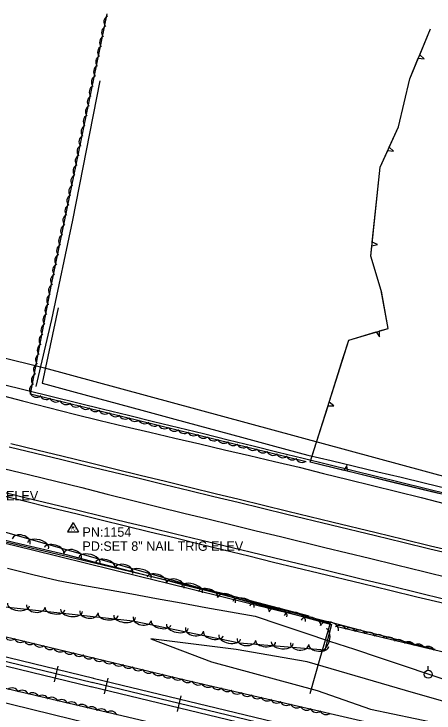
# Model space of a CAD drawing. Extents: x 1441650 to 1491889, y 345904 to 358319.
# Drawn here: x 1454791.4 to 1455015, y 352248.4 to 352621 of the extents above; entities that cross this region are included whole.
import ezdxf

# ---------------------------------------------------------------- set-up
doc = ezdxf.new("R2010")
doc.units = 0
for name, color, linetype in [('S_DITCHLINE', 7, 'Continuous'), ('S_EDGE_PAVEMENT', 7, 'Continuous'), ('S_PAVEMENT_CROWN', 7, 'Continuous'), ('S_RAILROAD', 7, 'Continuous'), ('S_SECONDARY_CTL', 7, 'Continuous'), ('S_SECONDARY_CTL_ANNOT', 7, 'Continuous'), ('S_SHOULDER', 7, 'Continuous'), ('S_STREAM', 7, 'Continuous'), ('S_TREE', 7, 'Continuous'), ('S_UTILITY_POLE', 7, 'Continuous'), ('S_UTL_PT_SYM', 7, 'Continuous'), ('S_WATER_UTILITIES', 7, 'Continuous')]:
    doc.layers.add(name, color=color, linetype=linetype)

msp = doc.modelspace()

# ---------------------------------------------------------------- linework, layer by layer
at = {"layer": 'S_DITCHLINE'}
for points in [[(1454784.38, 352423.88), (1454798.06, 352420.51), (1454811.75, 352417.13), (1454825.43, 352413.76), (1454839.11, 352410.38), (1454852.39, 352407.11), (1454865.67, 352403.83), (1454878.95, 352400.56), (1454892.23, 352397.28), (1454905.5, 352394.01), (1454918.78, 352390.73), (1454932.06, 352387.46), (1454945.34, 352384.18), (1454958.29, 352380.99), (1454971.24, 352377.8), (1454984.19, 352374.61), (1454997.14, 352371.42), (1455010.09, 352368.23), (1455023.04, 352365.04)], [(1454782.24, 352418.24), (1454796, 352414.73), (1454809.76, 352411.23), (1454823.53, 352407.72), (1454837.29, 352404.21), (1454850.54, 352401.1), (1454863.8, 352397.99), (1454877.05, 352394.88), (1454890.3, 352391.77), (1454903.55, 352388.66), (1454916.81, 352385.55), (1454930.06, 352382.45), (1454943.31, 352379.34), (1454956.28, 352376.1), (1454969.25, 352372.87), (1454982.22, 352369.64), (1454995.19, 352366.4), (1455008.16, 352363.17), (1455021.13, 352359.93)], [(1454778.21, 352342.58), (1454791.84, 352339.32), (1454805.47, 352336.06), (1454819.1, 352332.79), (1454831.95, 352329.52), (1454844.79, 352326.24), (1454857.63, 352322.96), (1454870.48, 352319.68), (1454883.32, 352316.4), (1454896.17, 352313.12), (1454909.01, 352309.84), (1454921.85, 352306.56), (1454935.24, 352303.1), (1454948.64, 352299.63), (1454962.03, 352296.17), (1454975.42, 352292.7), (1454988.81, 352289.24), (1455002.2, 352285.77), (1455015.59, 352282.31)], [(1454787.91, 352325.53), (1454801.39, 352322.23), (1454814.87, 352318.93), (1454827.98, 352316.55), (1454841.1, 352314.18), (1454854.21, 352311.81), (1454867.32, 352309.44), (1454880.44, 352307.06), (1454893.55, 352304.69), (1454906.67, 352302.32), (1454919.78, 352299.95), (1454933.01, 352295.54), (1454946.23, 352291.14), (1454959.46, 352286.73), (1454972.69, 352282.33), (1454985.91, 352277.92), (1454999.14, 352273.52), (1455012.37, 352269.11), (1455025.59, 352264.71)]]:
    msp.add_lwpolyline(points, dxfattribs=at)
at = {"layer": 'S_EDGE_PAVEMENT'}
for points in [[(1454788.75, 352390.31), (1454802.85, 352386.87), (1454816.94, 352383.43), (1454831.03, 352379.98), (1454844.51, 352376.74), (1454857.98, 352373.49), (1454871.46, 352370.24), (1454884.93, 352366.99), (1454897.86, 352363.84), (1454910.78, 352360.69), (1454923.71, 352357.54), (1454936.63, 352354.39), (1454960.28, 352348.65), (1454983.93, 352342.91), (1454998.39, 352339.42), (1455012.84, 352335.93), (1455027.29, 352332.43)], [(1454783.15, 352366.75), (1454797.23, 352363.31), (1454811.32, 352359.88), (1454825.41, 352356.44), (1454838.42, 352353.3), (1454851.43, 352350.16), (1454864.44, 352347.02), (1454877.46, 352343.88), (1454890.66, 352340.68), (1454903.87, 352337.48), (1454917.08, 352334.27), (1454930.29, 352331.07), (1454954.02, 352325.33), (1454977.75, 352319.59), (1454992.12, 352316.09), (1455006.5, 352312.6), (1455020.87, 352309.1)]]:
    msp.add_lwpolyline(points, dxfattribs=at)
at = {"layer": 'S_PAVEMENT_CROWN'}
msp.add_lwpolyline([(1454785.87, 352378.65), (1454799.75, 352375.26), (1454813.63, 352371.88), (1454827.51, 352368.49), (1454841.08, 352365.1), (1454854.65, 352361.71), (1454868.22, 352358.32), (1454881.79, 352354.93), (1454894.67, 352351.8), (1454907.55, 352348.66), (1454920.43, 352345.52), (1454933.31, 352342.39), (1454956.99, 352336.66), (1454980.66, 352330.94), (1454995.12, 352327.38), (1455009.57, 352323.82), (1455024.03, 352320.26)], dxfattribs=at)
at = {"layer": 'S_RAILROAD'}
for p, q in [((1454812.93, 352264.95), (1454814.98, 352273.38)), ((1454814.51, 352271.44), (1454814.49, 352271.33)), ((1454813.4, 352266.86), (1454813.41, 352266.89)), ((1454839.57, 352258.5), (1454841.61, 352266.93)), ((1454841.14, 352264.99), (1454841.11, 352264.89)), ((1454840.03, 352260.41), (1454840.04, 352260.45)), ((1454878.46, 352249.11), (1454880.49, 352257.54)), ((1454880.02, 352255.6), (1454880, 352255.49)), ((1454878.92, 352251.02), (1454878.93, 352251.05))]:
    msp.add_line(p, q, dxfattribs=at)
for points in [[(1454833.94, 352266.71), (1454392.82, 352374.01)], [(1454833.39, 352264.44), (1454392.26, 352371.74)], [(1454832.83, 352262.13), (1454391.7, 352369.44)], [(1454813.99, 352269.16), (1454813.96, 352269.16)], [(1455197.77, 352178.84), (1454833.57, 352266.82)], [(1455196.44, 352174.31), (1454832.46, 352262.24)], [(1455197.11, 352176.59), (1454833.02, 352264.55)], [(1454840.62, 352262.71), (1454840.59, 352262.72)], [(1454879.5, 352253.32), (1454879.47, 352253.32)]]:
    msp.add_lwpolyline(points, dxfattribs=at)
at = {"layer": 'S_SECONDARY_CTL'}
for p, q in [((1454822.83, 352349.94), (1454819.82, 352344.99)), ((1454822.83, 352349.94), (1454825.78, 352344.99)), ((1454819.82, 352344.99), (1454825.78, 352344.99))]:
    msp.add_line(p, q, dxfattribs=at)
for radius in [0.311, 0.183, 0.103]:
    msp.add_circle((1454822.83, 352347.33), radius, dxfattribs=at)
at = {"layer": 'S_SHOULDER'}
for points in [[(1454789.62, 352392.01), (1454803.56, 352388.61), (1454817.51, 352385.22), (1454831.45, 352381.82), (1454844.98, 352378.51), (1454858.5, 352375.2), (1454872.02, 352371.89), (1454885.54, 352368.58), (1454898.46, 352365.43), (1454911.37, 352362.27), (1454924.28, 352359.11), (1454937.2, 352355.95), (1454960.71, 352350.26), (1454984.22, 352344.57), (1454998.74, 352341.05), (1455013.25, 352337.53), (1455027.76, 352334.02)], [(1454782.72, 352364.85), (1454796.79, 352361.4), (1454810.86, 352357.95), (1454824.94, 352354.5), (1454837.89, 352351.34), (1454850.85, 352348.18), (1454863.8, 352345.02), (1454876.76, 352341.86), (1454889.96, 352338.61), (1454903.16, 352335.36), (1454916.36, 352332.11), (1454929.57, 352328.86), (1454953.29, 352323.12), (1454977.01, 352317.37), (1454991.47, 352313.86), (1455005.94, 352310.35), (1455020.41, 352306.83)]]:
    msp.add_lwpolyline(points, dxfattribs=at)
at = {"layer": 'S_STREAM'}
for points in [[(1454837.17, 352585.34), (1454822.46, 352511.1), (1454811.34, 352458.07), (1454803, 352422.49)], [(1454464.37, 352420.45), (1454584.76, 352390.45), (1454690.29, 352362.54), (1454900.85, 352312.56), (1454948.37, 352300.12)], [(1454471.1, 352326.84), (1454549.18, 352306.79), (1454623.89, 352291.03), (1454691.51, 352277.03), (1454779.52, 352255.49), (1454832.51, 352242.57), (1454893.03, 352228.02), (1454923.09, 352220.41), (1454992.68, 352203.26), (1455037.86, 352193.79)], [(1455059.44, 352243.37), (1455004.1, 352259.04), (1454947.56, 352275.57), (1454909.7, 352282.22), (1454864.17, 352287.88), (1454896.48, 352275.7), (1454952.86, 352260.44), (1454981.16, 352250.46), (1455040.76, 352237.99)]]:
    msp.add_lwpolyline(points, dxfattribs=at)
at = {"layer": 'S_TREE'}
for p, q in [((1455006.66, 352597.38), (1455009.79, 352597.1)), ((1455009.79, 352597.1), (1455007.42, 352599.2)), ((1454993.49, 352547.88), (1454991.18, 352550.06)), ((1454990.37, 352548.27), (1454993.49, 352547.88)), ((1454981.96, 352497.42), (1454985.04, 352498.05)), ((1454985.04, 352498.05), (1454982.16, 352499.37)), ((1454985.98, 352448.89), (1454986.1, 352452.05)), ((1454984.22, 352451.49), (1454985.98, 352448.89)), ((1454958.61, 352412.13), (1454961.75, 352412.13)), ((1454961.75, 352412.13), (1454959.2, 352414.01)), ((1454968.69, 352380.35), (1454966.99, 352377.68)), ((1454968.9, 352377.22), (1454968.69, 352380.35))]:
    msp.add_line(p, q, dxfattribs=at)
for points in [[(1454946.93, 352382.34), (1454800.22, 352418.34), (1454811.34, 352476.73), (1454825.66, 352546.64), (1454841.04, 352620.99)], [(1455082.97, 352349.51), (1454949.08, 352382.03), (1454969.69, 352447.17), (1454990.66, 352453.41), (1454986.98, 352473.63), (1454981.39, 352491.91), (1454986.32, 352539.42), (1454996.11, 352560.81), (1455002.09, 352586.46), (1455013.21, 352613.03)], [(1455007.42, 352599.2), (1455013.21, 352613.03)], [(1454999.1, 352573.64), (1455002.09, 352586.46), (1455006.66, 352597.38)], [(1454991.18, 352550.06), (1454996.11, 352560.81), (1454999.1, 352573.64)], [(1454984.74, 352524.24), (1454986.32, 352539.42), (1454990.37, 352548.27)], [(1454982.16, 352499.37), (1454984.74, 352524.24)], [(1454987.05, 352473.3), (1454986.98, 352473.63), (1454981.39, 352491.91), (1454981.96, 352497.42)], [(1454986.1, 352452.05), (1454990.66, 352453.41), (1454987.05, 352473.3)], [(1454814.94, 352464.41), (1454810.63, 352444.28), (1454806.32, 352424.15), (1454824.01, 352419.36), (1454841.7, 352414.58), (1454859.39, 352409.79), (1454877.07, 352405), (1454894.76, 352400.21), (1454912.45, 352395.42), (1454930.14, 352390.63), (1454947.82, 352385.84), (1454960.24, 352382.88), (1454972.65, 352379.92), (1454985.07, 352376.96), (1454997.48, 352374.01), (1455009.89, 352371.05), (1455022.31, 352368.09)], [(1454814.94, 352464.41), (1454810.63, 352444.28), (1454806.32, 352424.15), (1454824.01, 352419.36), (1454841.7, 352414.58), (1454859.39, 352409.79), (1454877.07, 352405), (1454894.76, 352400.21), (1454912.45, 352395.42), (1454930.14, 352390.63), (1454947.82, 352385.84), (1454960.24, 352382.88), (1454972.65, 352379.92), (1454985.07, 352376.96), (1454997.48, 352374.01), (1455009.89, 352371.05), (1455022.31, 352368.09)], [(1454966.74, 352437.84), (1454969.69, 352447.17), (1454984.22, 352451.49)], [(1454959.2, 352414.01), (1454966.74, 352437.84)], [(1454951.07, 352388.3), (1454958.61, 352412.13)], [(1454608.66, 352342.73), (1454569.35, 352351.26), (1454556.38, 352364.74), (1454562.37, 352384.23), (1454599.48, 352385.45), (1454764.41, 352351.11), (1454910.03, 352309.37), (1454960.45, 352295.62), (1454956.96, 352281.83), (1454911.55, 352285.58), (1454854.61, 352297.28), (1454786.67, 352304.84), (1454727.92, 352320.28), (1454664.77, 352330.43), (1454609.68, 352342.06)], [(1454966.99, 352377.68), (1454949.08, 352382.03), (1454951.07, 352388.3)], [(1454993.19, 352371.32), (1454968.9, 352377.22)], [(1454962.69, 352294.69), (1455082.43, 352265.99), (1455127.73, 352260.33), (1455171.95, 352246.67), (1455237.79, 352229.12), (1455266.56, 352215.9), (1455276.91, 352188.42), (1455269.69, 352172.72), (1455130.94, 352204.71), (1454988.1, 352241.29), (1454883.15, 352265.69), (1454742.86, 352299.41), (1454579.09, 352337.35), (1454448.11, 352370.53)], [(1455017.48, 352365.42), (1454993.19, 352371.32)], [(1454786.75, 352338.93), (1454801.16, 352335.37), (1454815.57, 352331.82), (1454829.99, 352328.27), (1454844.4, 352324.71), (1454858.82, 352321.16), (1454873.23, 352317.61), (1454887.65, 352314.05), (1454902.06, 352310.5), (1454916.48, 352306.94), (1454930.89, 352303.39), (1454945.3, 352299.84), (1454959.72, 352296.28), (1454954.33, 352277.44), (1454948.95, 352258.59)], [(1454786.75, 352338.93), (1454801.16, 352335.37), (1454815.57, 352331.82), (1454829.99, 352328.27), (1454844.4, 352324.71), (1454858.82, 352321.16), (1454873.23, 352317.61), (1454887.65, 352314.05), (1454902.06, 352310.5), (1454916.48, 352306.94), (1454930.89, 352303.39), (1454945.3, 352299.84), (1454959.72, 352296.28), (1454954.33, 352277.44), (1454948.95, 352258.59)], [(1454720.16, 352277.33), (1454872.99, 352241.33), (1454943.73, 352222.23), (1454977.97, 352214.82), (1455025.42, 352203.17), (1455102.25, 352183.63), (1455122.31, 352178.67), (1455138.5, 352175.87), (1455168.52, 352169.53), (1455253.06, 352148.2), (1455262.5, 352142.36), (1455264.98, 352131.4), (1455261.62, 352116.37)]]:
    msp.add_lwpolyline(points, dxfattribs=at)
for centre in [(1454842.86, 352616.65), (1454841.69, 352611.12), (1454840.58, 352605.8), (1454839.54, 352600.6), (1454838.54, 352595.41), (1454837.39, 352590.2), (1454836.21, 352584.68), (1454835.11, 352579.35), (1454834.07, 352574.15), (1454833.07, 352568.96), (1454831.92, 352563.75), (1454830.74, 352558.23), (1454829.64, 352552.9), (1454828.6, 352547.7)]:
    msp.add_arc(centre, 3.64, 117.5122, 219.1091, dxfattribs=at)
for centre, major_axis, ratio, start_param, end_param in [((1454827.61, 352542.51), (-3.63, 0.35), 0.999968, 5.289411, 7.062612), ((1454826.46, 352537.3), (-3.63, 0.35), 0.999968, 5.289411, 7.062612), ((1454825.3, 352531.78), (-3.63, 0.35), 0.999968, 5.289411, 7.062612), ((1454824.2, 352526.45), (-3.63, 0.35), 0.999968, 5.289411, 7.062612), ((1454823.17, 352521.25), (-3.63, 0.35), 0.999968, 5.289411, 7.062612), ((1454822.19, 352516.06), (-3.63, 0.35), 0.999968, 5.289411, 7.062612), ((1454821.04, 352510.85), (-3.63, 0.35), 0.999968, 5.289411, 7.062612), ((1454819.88, 352505.32), (-3.63, 0.35), 0.999968, 5.289411, 7.062612), ((1454818.78, 352499.99), (-3.63, 0.35), 0.999968, 5.289411, 7.062612), ((1454817.75, 352494.79), (-3.63, 0.35), 0.999968, 5.289411, 7.062612), ((1454816.76, 352489.6), (-3.63, 0.35), 0.999968, 5.289411, 7.062612), ((1454815.62, 352484.39), (-3.63, 0.35), 0.999968, 5.289411, 7.062612), ((1454814.46, 352478.86), (-3.63, 0.35), 0.999968, 5.289411, 7.062612), ((1454813.41, 352473.56), (3.6, -0.58), 0.99965, 2.227985, 4.001186), ((1454812.45, 352468.35), (3.6, -0.58), 0.99965, 2.227985, 4.001186), ((1454811.53, 352463.15), (3.6, -0.58), 0.99965, 2.227985, 4.001186), ((1454810.46, 352457.92), (3.6, -0.58), 0.99965, 2.227985, 4.001186), ((1454809.38, 352452.38), (3.6, -0.58), 0.99965, 2.227985, 4.001186), ((1454808.36, 352447.04), (3.6, -0.58), 0.99965, 2.227985, 4.001186), ((1454807.4, 352441.82), (3.6, -0.58), 0.99965, 2.227985, 4.001186), ((1454806.48, 352436.62), (3.6, -0.58), 0.99965, 2.227985, 4.001186), ((1454805.41, 352431.4), (3.6, -0.58), 0.99965, 2.227985, 4.001186), ((1454804.32, 352425.86), (3.6, -0.58), 0.99965, 2.227985, 4.001186), ((1454803.3, 352420.52), (3.6, -0.58), 0.99965, 2.227985, 4.001186), ((1454803.36, 352420.3), (3.62, -0.43), 0.999946, 3.704552, 5.477752), ((1454808.51, 352419.12), (3.62, -0.43), 0.999946, 3.704552, 5.477752), ((1454813.67, 352417.77), (3.62, -0.43), 0.999946, 3.704552, 5.477752), ((1454819.15, 352416.4), (3.62, -0.43), 0.999946, 3.704552, 5.477752), ((1454824.43, 352415.1), (3.62, -0.43), 0.999946, 3.704552, 5.477752), ((1454829.59, 352413.87), (3.62, -0.43), 0.999946, 3.704552, 5.477752), ((1454834.74, 352412.68), (3.62, -0.43), 0.999946, 3.704552, 5.477752), ((1454839.9, 352411.34), (3.62, -0.43), 0.999946, 3.704552, 5.477752), ((1454845.38, 352409.96), (3.62, -0.43), 0.999946, 3.704552, 5.477752), ((1454850.66, 352408.66), (3.62, -0.43), 0.999946, 3.704552, 5.477752), ((1454855.82, 352407.43), (3.62, -0.43), 0.999946, 3.704552, 5.477752), ((1454860.97, 352406.24), (3.62, -0.43), 0.999946, 3.704552, 5.477752), ((1454866.13, 352404.9), (3.62, -0.43), 0.999946, 3.704552, 5.477752), ((1454871.61, 352403.52), (3.62, -0.43), 0.999946, 3.704552, 5.477752), ((1454876.89, 352402.22), (3.62, -0.43), 0.999946, 3.704552, 5.477752), ((1454882.05, 352401), (3.62, -0.43), 0.999946, 3.704552, 5.477752), ((1454887.2, 352399.81), (3.62, -0.43), 0.999946, 3.704552, 5.477752), ((1454892.36, 352398.47), (3.62, -0.43), 0.999946, 3.704552, 5.477752), ((1454897.84, 352397.09), (3.62, -0.43), 0.999946, 3.704552, 5.477752), ((1454903.12, 352395.79), (3.62, -0.43), 0.999946, 3.704552, 5.477752), ((1454908.28, 352394.56), (3.62, -0.43), 0.999946, 3.704552, 5.477752), ((1454913.43, 352393.37), (3.62, -0.43), 0.999946, 3.704552, 5.477752), ((1454918.59, 352392.03), (3.62, -0.43), 0.999946, 3.704552, 5.477752), ((1454924.07, 352390.65), (3.62, -0.43), 0.999946, 3.704552, 5.477752), ((1454929.35, 352389.35), (3.62, -0.43), 0.999946, 3.704552, 5.477752), ((1454934.51, 352388.12), (3.62, -0.43), 0.999946, 3.704552, 5.477752), ((1454939.66, 352386.94), (3.62, -0.43), 0.999946, 3.704552, 5.477752), ((1454944.82, 352385.59), (3.62, -0.43), 0.999946, 3.704552, 5.477752), ((1454795.23, 352339.8), (-4.76, 1.36), 0.685348, 3.141427, 6.283019), ((1454804.2, 352337.5), (-5.64, 1.62), 0.55011, 3.141491, 6.283084), ((1454812.72, 352335.06), (-5.14, 1.47), 0.540729, 3.141495, 6.283087), ((1454822.55, 352331.97), (-4.76, 1.36), 0.685348, 3.141427, 6.283019), ((1454831.52, 352329.67), (-5.64, 1.62), 0.55011, 3.141491, 6.283084), ((1454840.04, 352327.23), (-5.14, 1.47), 0.540729, 3.141495, 6.283087), ((1454849.87, 352324.14), (-4.76, 1.36), 0.685348, 3.141427, 6.283019), ((1454858.85, 352321.84), (-5.64, 1.62), 0.55011, 3.141491, 6.283084), ((1454867.37, 352319.39), (-5.14, 1.47), 0.540729, 3.141495, 6.283087), ((1454877.2, 352316.3), (-4.76, 1.36), 0.685348, 3.141427, 6.283019), ((1454886.17, 352314), (-5.64, 1.62), 0.55011, 3.141491, 6.283084), ((1454894.69, 352311.56), (-5.14, 1.47), 0.540729, 3.141495, 6.283087), ((1454904.52, 352308.47), (-4.76, 1.36), 0.685348, 3.141427, 6.283019), ((1454793.79, 352306.18), (5.83, -0.65), 0.550048, 3.141593, 6.283185), ((1454913.53, 352306.22), (-5.66, 1.54), 0.550265, 3.141389, 6.282982), ((1454922.09, 352303.88), (-5.16, 1.41), 0.540882, 3.141396, 6.282988), ((1454803.02, 352305.42), (4.92, -0.55), 0.685272, 3.141593, 6.283185), ((1454813.23, 352304.02), (5.31, -0.59), 0.540668, 3.141593, 6.283185), ((1454822.05, 352303.04), (5.83, -0.65), 0.550048, 3.141593, 6.283185), ((1454931.95, 352300.92), (-4.78, 1.3), 0.685542, 3.141259, 6.282852), ((1454831.28, 352302.28), (4.92, -0.55), 0.685272, 3.141593, 6.283185), ((1454841.49, 352300.88), (5.31, -0.59), 0.540668, 3.141593, 6.283185), ((1454850.3, 352299.9), (5.83, -0.65), 0.550048, 3.141593, 6.283185), ((1454859.68, 352298.67), (4.85, -1), 0.685277, 3.141593, 6.283185), ((1454940.95, 352298.74), (-5.66, 1.54), 0.550265, 3.141389, 6.282982), ((1454949.5, 352296.41), (-5.16, 1.41), 0.540882, 3.141396, 6.282988), ((1454869.72, 352296.34), (5.24, -1.08), 0.540673, 3.141593, 6.283185), ((1454878.4, 352294.56), (5.75, -1.18), 0.550053, 3.141593, 6.283185), ((1454959.37, 352293.45), (-4.78, 1.3), 0.685542, 3.141259, 6.282852), ((1454887.52, 352292.95), (4.85, -1), 0.685277, 3.141593, 6.283185), ((1454897.56, 352290.62), (5.24, -1.08), 0.540673, 3.141593, 6.283185), ((1454956.24, 352287.62), (1.44, 5.69), 0.550056, 3.141593, 6.283185), ((1454964.82, 352291.45), (-3.54, 0.85), 0.999998, 3.825788, 5.598989), ((1454969.99, 352290.13), (-3.54, 0.85), 0.999998, 3.825788, 5.598989), ((1454975.14, 352288.97), (-3.54, 0.85), 0.999998, 3.825788, 5.598989), ((1454789.63, 352290.87), (2.01, 3.04), 0.999981, 2.602887, 4.376088), ((1454794.79, 352289.66), (2.01, 3.04), 0.999981, 2.602887, 4.376088), ((1454906.25, 352288.83), (5.75, -1.18), 0.550053, 3.141593, 6.283185), ((1454915.14, 352287.67), (4.94, -0.41), 0.68527, 3.1416, 6.283192), ((1454980.31, 352287.77), (-3.54, 0.85), 0.999998, 3.825789, 5.598989), ((1454985.6, 352286.5), (-3.54, 0.85), 0.999998, 3.825789, 5.598989), ((1454991.08, 352285.15), (-3.54, 0.85), 0.999998, 3.825788, 5.598989), ((1454799.94, 352288.5), (2.01, 3.04), 0.999981, 2.602887, 4.376088), ((1454805.11, 352287.18), (2.01, 3.04), 0.999981, 2.602887, 4.376088), ((1454810.6, 352285.83), (2.01, 3.04), 0.999981, 2.602887, 4.376088), ((1454925.39, 352286.57), (5.33, -0.44), 0.540667, 3.141597, 6.283189), ((1454934.23, 352285.83), (5.85, -0.48), 0.550047, 3.141597, 6.28319), ((1454943.48, 352285.33), (4.94, -0.41), 0.68527, 3.1416, 6.283192), ((1454953.72, 352284.22), (5.33, -0.44), 0.540667, 3.141597, 6.283189), ((1454996.25, 352283.84), (-3.54, 0.85), 0.999998, 3.825788, 5.598989), ((1455001.41, 352282.68), (-3.54, 0.85), 0.999998, 3.825788, 5.598989), ((1455006.57, 352281.48), (-3.54, 0.85), 0.999998, 3.825789, 5.598989), ((1454815.89, 352284.55), (2.01, 3.04), 0.999981, 2.602887, 4.376088), ((1454821.05, 352283.35), (2.01, 3.04), 0.999981, 2.602887, 4.376088), ((1454826.2, 352282.19), (2.01, 3.04), 0.999981, 2.602887, 4.376088), ((1455011.87, 352280.2), (-3.54, 0.85), 0.999998, 3.825789, 5.598989), ((1454831.37, 352280.87), (2.01, 3.04), 0.999981, 2.602887, 4.376088), ((1454836.86, 352279.52), (2.01, 3.04), 0.999981, 2.602887, 4.376088), ((1454842.15, 352278.24), (2.01, 3.04), 0.999981, 2.602887, 4.376088), ((1454847.31, 352277.04), (2.01, 3.04), 0.999981, 2.602887, 4.376088), ((1454852.46, 352275.87), (2.01, 3.04), 0.999981, 2.602887, 4.376088), ((1454857.63, 352274.55), (2.01, 3.04), 0.999981, 2.602887, 4.376088), ((1454863.12, 352273.2), (2.01, 3.04), 0.999981, 2.602887, 4.376088), ((1454868.41, 352271.93), (2.01, 3.04), 0.999981, 2.602887, 4.376088), ((1454873.57, 352270.72), (2.01, 3.04), 0.999981, 2.602887, 4.376088), ((1454878.72, 352269.56), (2.01, 3.04), 0.999981, 2.602887, 4.376088), ((1454883.87, 352268.25), (-0.44, -3.62), 0.9998, 5.290328, 7.063529), ((1454790.38, 352258.09), (-1.24, 3.43), 0.999948, 4.818601, 6.591801), ((1454889.37, 352266.94), (-0.44, -3.62), 0.9998, 5.290328, 7.063529), ((1454894.66, 352265.7), (-0.44, -3.62), 0.9998, 5.290328, 7.063529), ((1454899.84, 352264.54), (-0.44, -3.62), 0.9998, 5.290328, 7.063529), ((1454795.68, 352256.84), (-1.24, 3.43), 0.999948, 4.818601, 6.591801), ((1454801.16, 352255.52), (-1.24, 3.43), 0.999948, 4.818601, 6.591801), ((1454905, 352263.41), (-0.44, -3.62), 0.9998, 5.290328, 7.063529), ((1454910.18, 352262.13), (-0.44, -3.62), 0.9998, 5.290328, 7.063529), ((1454915.67, 352260.82), (-0.44, -3.62), 0.9998, 5.290328, 7.063529), ((1454806.34, 352254.22), (-1.24, 3.43), 0.999948, 4.818601, 6.591801), ((1454811.5, 352253.08), (-1.24, 3.43), 0.999948, 4.818601, 6.591801), ((1454816.67, 352251.9), (-1.24, 3.43), 0.999948, 4.818601, 6.591801), ((1454821.96, 352250.65), (-1.24, 3.43), 0.999948, 4.818601, 6.591801), ((1454920.97, 352259.59), (-0.44, -3.62), 0.9998, 5.290328, 7.063529), ((1454926.14, 352258.42), (-0.44, -3.62), 0.9998, 5.290328, 7.063529), ((1454931.3, 352257.3), (-0.44, -3.62), 0.9998, 5.290328, 7.063529), ((1454827.45, 352249.32), (-1.24, 3.43), 0.999948, 4.818601, 6.591801), ((1454832.63, 352248.03), (-1.24, 3.43), 0.999948, 4.818601, 6.591801), ((1454936.48, 352256.02), (-0.44, -3.62), 0.9998, 5.290328, 7.063529), ((1454941.97, 352254.71), (-0.44, -3.62), 0.9998, 5.290328, 7.063529), ((1454947.27, 352253.47), (-0.44, -3.62), 0.9998, 5.290328, 7.063529), ((1454952.44, 352252.31), (-0.44, -3.62), 0.9998, 5.290328, 7.063529), ((1454837.79, 352246.89), (-1.24, 3.43), 0.999948, 4.818601, 6.591801), ((1454842.96, 352245.71), (-1.24, 3.43), 0.999948, 4.818601, 6.591801), ((1454957.6, 352251.18), (-0.44, -3.62), 0.9998, 5.290328, 7.063529)]:
    msp.add_ellipse(centre, major_axis=major_axis, ratio=ratio, start_param=start_param, end_param=end_param, dxfattribs=at)
at = {"layer": 'S_UTILITY_POLE'}
msp.add_line((1455011.86, 352271.15), (1455011.86, 352273.26), dxfattribs=at)
msp.add_circle((1455011.99, 352269.01), 2.13, dxfattribs=at)
at = {"layer": 'S_UTL_PT_SYM'}
msp.add_lwpolyline([(1454807.63, 352432.32), (1454807.63, 352432.37), (1454807.63, 352432.32), (1454807.58, 352432.32), (1454807.63, 352432.32), (1454807.63, 352432.27), (1454807.63, 352432.32), (1454807.68, 352432.32)], dxfattribs=at)
at = {"layer": 'S_WATER_UTILITIES'}
for p, q in [((1454599.79, 352483.48), (1454807.63, 352432.32)), ((1454807.63, 352432.32), (1455072.67, 352360.23))]:
    msp.add_line(p, q, dxfattribs=at)

# ---------------------------------------------------------------- texts
at = {"layer": 'S_SECONDARY_CTL'}
msp.add_text('TV', height=1.5, rotation=360, dxfattribs=at).set_placement((1454821.63, 352345.32))
at = {"layer": 'S_SECONDARY_CTL_ANNOT'}
for s, p in [('PD:SET 8" NAIL TRIG ELEV', (1454718.67, 352361.65)), ('PN:1154', (1454827.83, 352342.33)), ('PD:SET 8" NAIL TRIG ELEV', (1454827.83, 352334.83))]:
    msp.add_text(s, height=5, dxfattribs=at).set_placement(p)

doc.saveas('drawing.dxf')
